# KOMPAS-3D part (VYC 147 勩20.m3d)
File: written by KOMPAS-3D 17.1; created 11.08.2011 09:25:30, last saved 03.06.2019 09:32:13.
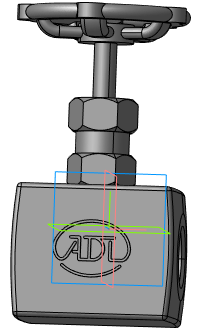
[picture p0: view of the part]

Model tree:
1. Плоскость XY
2. Плоскость ZX
3. Плоскость ZY
4. Ось X
5. Ось Y
6. Ось Z
7. Начало координат
8. Операция без истории:2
